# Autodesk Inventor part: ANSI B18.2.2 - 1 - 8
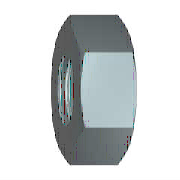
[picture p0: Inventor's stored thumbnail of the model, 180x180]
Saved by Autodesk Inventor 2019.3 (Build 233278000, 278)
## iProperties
Created: 2018-01
Part Number: ANSI B18.2.2 - 1 - 8
Material: Steel, Mild
Description: Hex Nuts (Inch Series) Heavy Hex Nut
Document SubType Name: Modeling
Standard: ANSI B18.2.2
Designer: u1426
Standard Revision: 2010
Standards Organization: ANSI
Language: en-US
Size Designation: 1 - 8
Categories: <MemberInstance><Categories><Category DisplayName="Fasteners" InternalName="e4da775c-781d-43d5-af7c-5136215cf5a6" Mnemonic="FSTN"><Category DisplayName="Nuts" I
Density: 7.85 g/cm^3
Appearance: Semi-Polished
IsCustomPart: 0
Author: u1426
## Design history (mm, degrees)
sketch "Sketch1"
  geometry: L1 (-23.83, 0)-(-11.915, 20.637); L2 (-11.915, 20.637)-(11.915, 20.637); L3 (11.915, 20.637)-(23.83, 0); L4 (23.83, 0)-(11.915, -20.638); L5 (11.915, -20.638)-(-11.915, -20.638); L6 (-11.915, -20.638)-(-23.83, 0); 2 further points
  constraints: 12 end point, 1 coincident, 1 horizontal, 11 other
  dimensions: "d0" = 47.66026 distance of L3.end L1.start (= 1.1547 x SW)
extrude "Body" new body sketch "Sketch1" distance "d1" = 24.9936 (= KOH); taper "d2" = 0 deg
sketch "Sketch2"
  geometry: L1 (0, 11.915)-(0, 23.83) reference; L2 (0, 23.83)-(24.994, 23.83) reference; L3 (24.994, 11.915)-(24.994, 23.83) reference; L4 (-4.999, 0)-(29.992, 0) reference; L5 (1.489, 23.83)-(0, 20.638); L6 (23.505, 23.83)-(24.994, 20.638)
  constraints: 4 end point, 4 point on line
  dimensions: "d3" = 25 deg angle of L1 L5 (= ANG1); "d4" = 25 deg angle of L3 L6 (= ANG2); "d5" = 41.275 diameter of L5.end L4 (= SW0); "d6" = 41.275 diameter of L6.end L4 (= SW01)
revolve "Chamfer1" sketch "Sketch2" stored, may be unused: angle "d7" = 90 deg
sketch "Sketch3"
  geometry: A1 r 20.638 centre (0, 0) between (-10.319, -17.873) and (10.319, -17.873) reference; 1 further point
  constraints: 1 coincident
hole "Thread" sketch "Sketch3" at (0, 0) diameter "d25" = 21.971; stored, may be unused: countersink angle "d29" = 82 deg, drill point angle "d31" = 118 deg; dims "d26" = 6, "d27" = 4, "d28" = 2, "d30" = 8
workaxis "Work Axis1"
workplane "Work Plane1"
body "Solid1"
chamfer "Chamfer2" distance "d8" = 1.71852 (= -0.5 x GD1 + 0.5 x NND); stored, may be unused: angle "d9" = 30 deg, second distance "d40" = 1.71852 (= -0.5 x GD1 + 0.5 x NND)
chamfer "Chamfer3" distance "d10" = 1.71852 (= -0.5 x GD1 + 0.5 x NND); stored, may be unused: angle "d11" = 30 deg, second distance "d41" = 1.71852 (= -0.5 x GD1 + 0.5 x NND)
other parameters: "ANG1" = 25 deg [user parameter; used in 1 equation term], "ANG2" = 25 deg [user parameter; used in 1 equation term], "NND" = 25.4 [user parameter; used in 4 equation terms], "KOH" = 24.9936 [user parameter; used in 1 equation term], "SW" = 41.275 [user parameter; used in 4 equation terms], "SW0" = 41.275 (= SW) [user parameter; used in 1 equation term], "SW01" = 41.275 (= SW) [user parameter; used in 1 equation term], "GD1" = 21.96296 (computed from THREADDIA, PTC, TOA) [user parameter; used in 4 equation terms], "d13" = 0, "d14" = 0, "d39" = 0, "d42" = 0, "THREADDIA" = 25.4 [user parameter; used in 1 equation term], "TOA" = 30 deg [user parameter; used in 1 equation term], "PTC" = 3.175 (computed from TPU) [user parameter; used in 1 equation term], "E0" = 47.67263 (= 1.155 x SW) [user parameter]
